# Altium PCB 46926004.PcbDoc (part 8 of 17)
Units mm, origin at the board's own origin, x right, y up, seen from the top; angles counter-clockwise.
Board outline 250 x 200 mm, 6 copper layers (Top Layer, INT1_GND, INT2_SIG, INT3_SIG, INT4_GND, Bottom Layer), stack 1.71 mm thick; 1450 components, 1293 nets, 5656 pads, 2307 vias.
Unrouted connection lines stored in the file: 2.
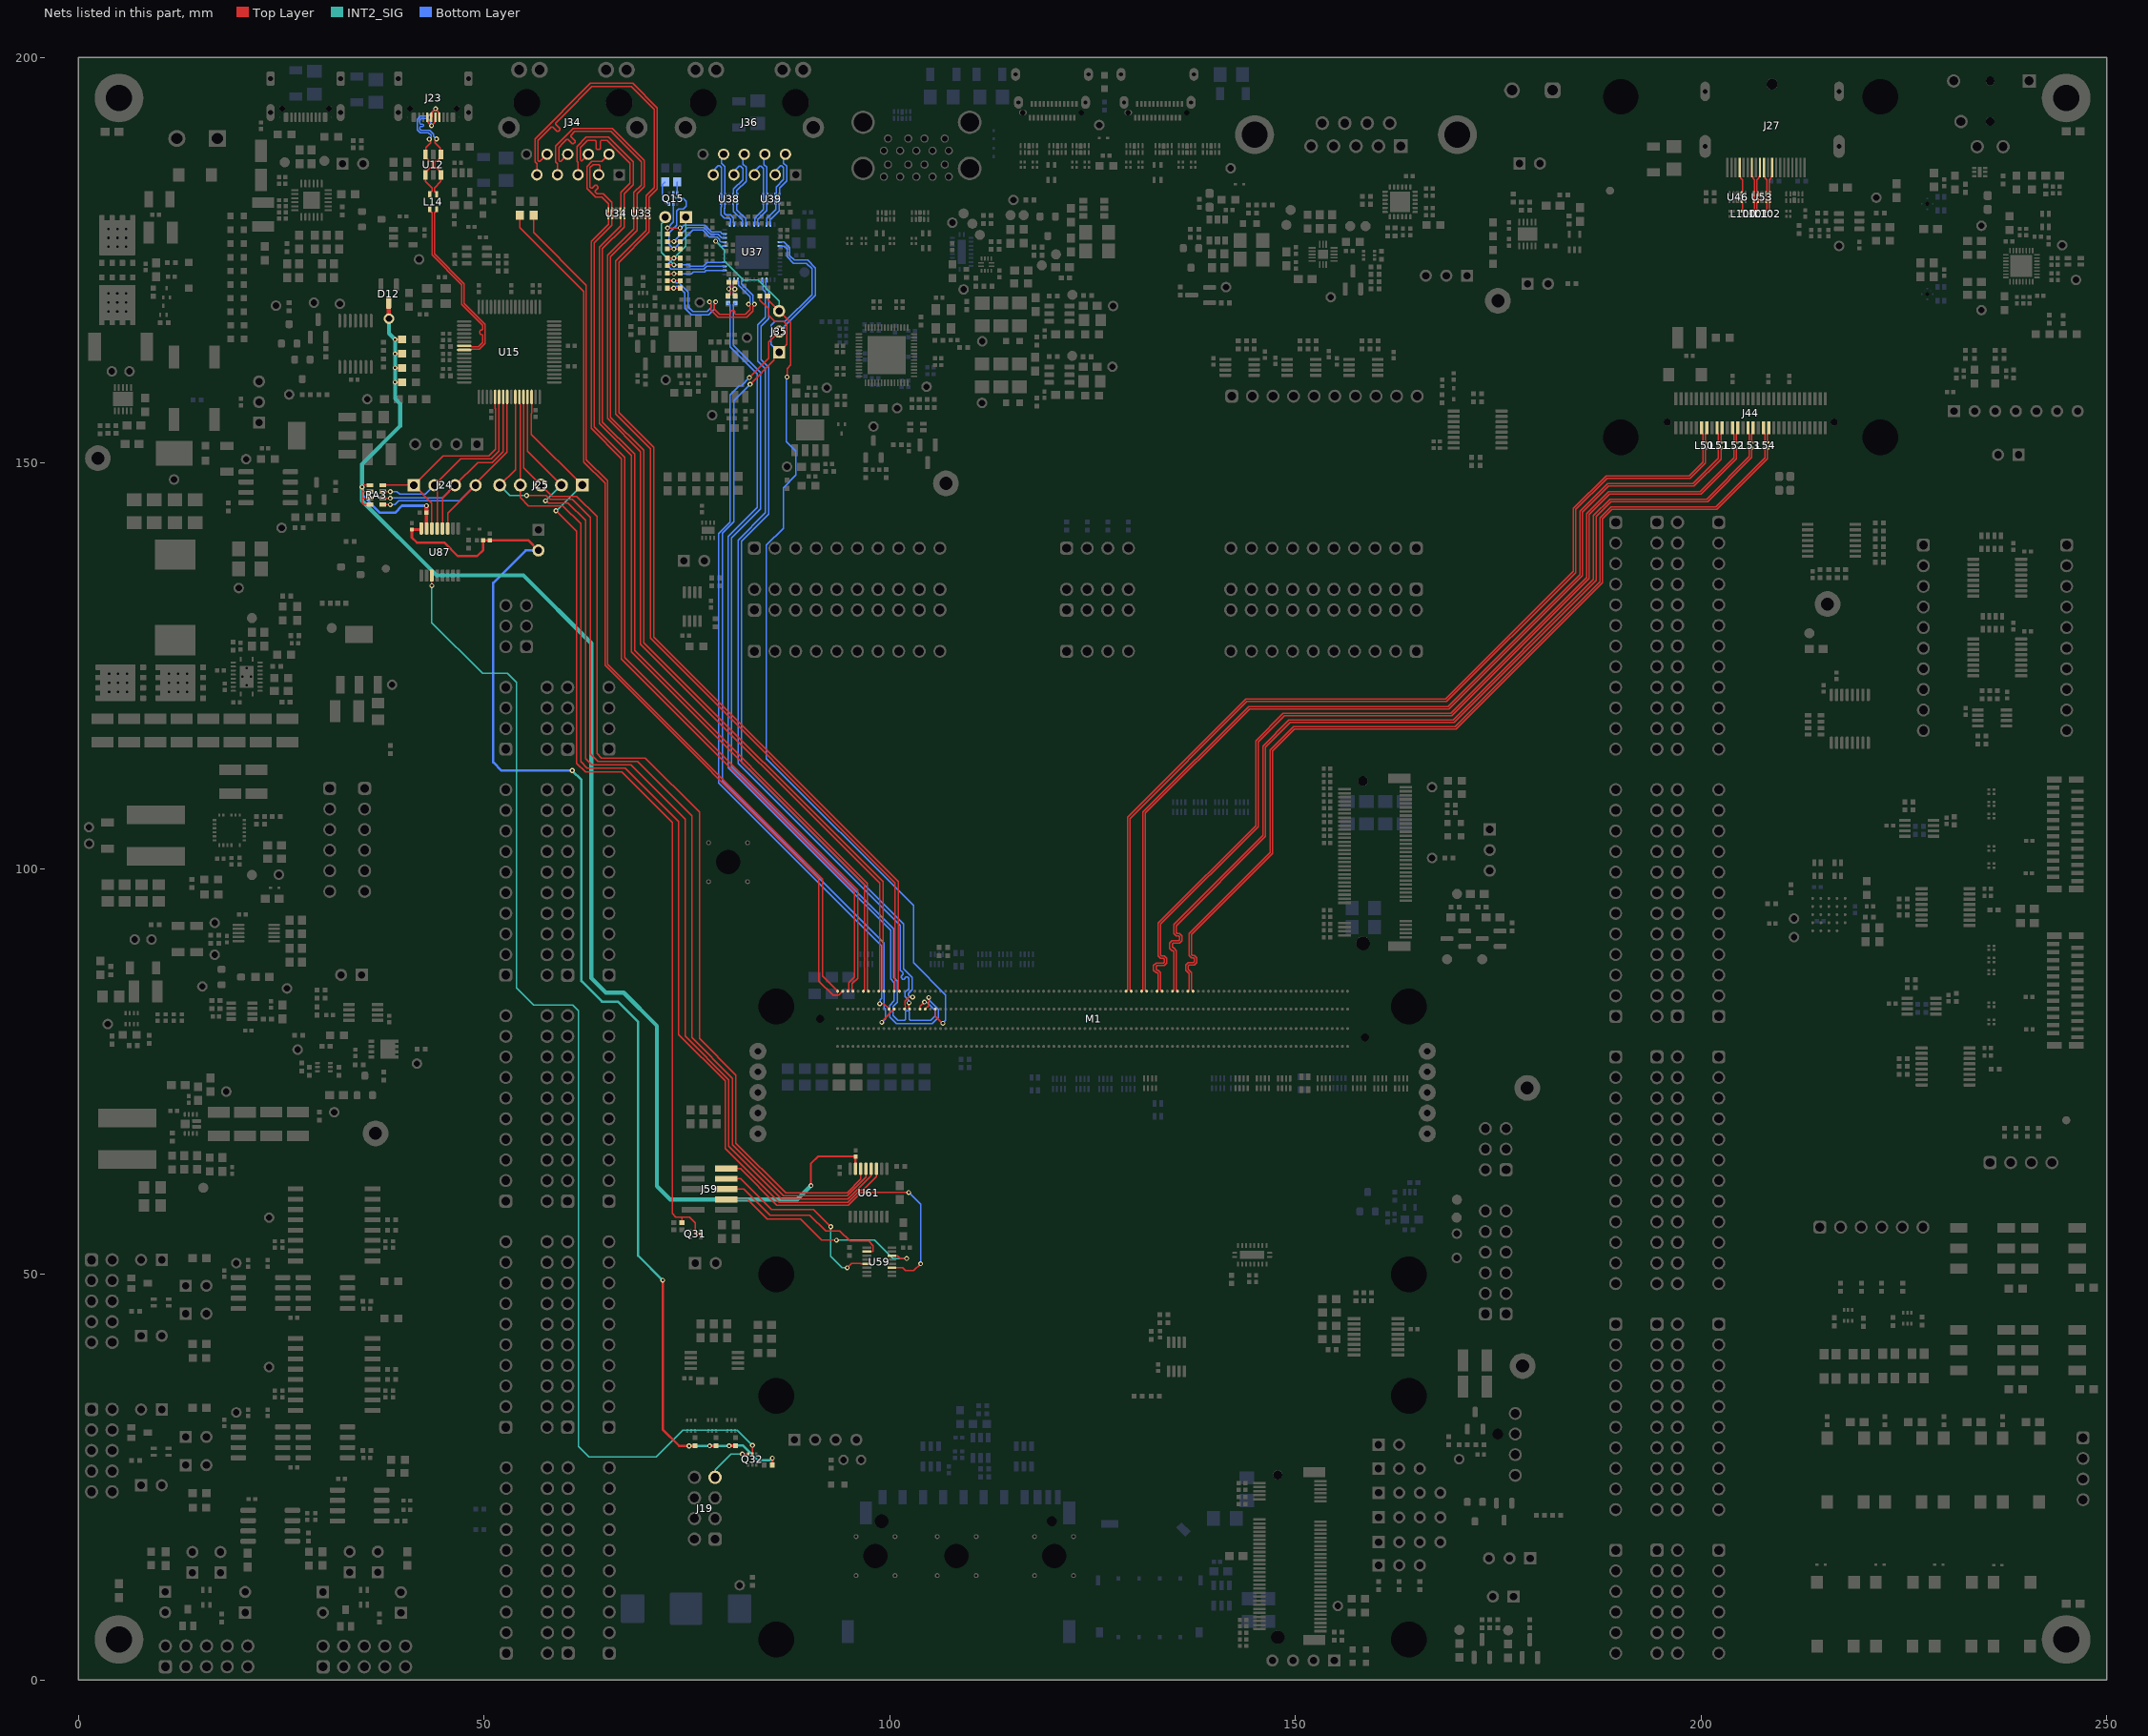
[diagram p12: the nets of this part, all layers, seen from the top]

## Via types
v1: diameter 0.6, hole 0.3, Top Layer to Bottom Layer, tented both sides, 2171 vias
v2: diameter 0.6, hole 0.3, Top Layer to Bottom Layer, 48 vias
v3: diameter 1, hole 0.5, Top Layer to Bottom Layer, tented both sides, 37 vias
v4: diameter 0.5, hole 0.2, Top Layer to Bottom Layer, tented both sides, 34 vias
v5: diameter 0.6, hole 0.3, Top Layer to Bottom Layer, tented bottom, 17 vias

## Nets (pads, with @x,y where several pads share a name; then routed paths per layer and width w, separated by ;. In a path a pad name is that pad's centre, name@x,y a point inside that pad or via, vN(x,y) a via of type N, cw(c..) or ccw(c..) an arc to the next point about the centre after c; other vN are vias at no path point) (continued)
DP__1_LANE1_P: J27.4 L100.4 U46.4 U46.7 | length 5.7
  Top Layer w0.15: J27.4@204.75,186.427 204.75,185.367 204.885,185.232 204.885,185.134 205.1,184.919 205.1,183.943 205.1,183.464 205,183.364 U46.7@205,183.184 205,183.004 205.1,182.904 205.1,182.631 205,182.53 U46.4@205,182.35 205,182.17 205.1,182.07 205.1,181.23 205.075,181.205 205.075,181.117 L100.4@205,181.043
DP__1_LANE2_N: J27.9 L101.3 U53.2 U53.9 | length 5.7
  Top Layer w0.15: L101.3@207,181.043 206.925,181.117 206.925,181.205 206.9,181.23 206.9,182.07 207,182.17 U53.2@207,182.35 207,182.53 206.9,182.63 206.9,182.904 207,183.004 U53.9@207,183.184 207,183.364 206.9,183.464 206.9,184.068 206.9,184.919 207.115,185.134 207.115,185.232 207.25,185.367 J27.9@207.25,186.427
DP__1_LANE2_P: J27.7 L101.4 U53.1 U53.10 | length 5.7
  Top Layer w0.15: J27.7@206.25,186.427 206.25,185.367 206.385,185.232 206.385,185.134 206.6,184.919 206.6,183.943 206.6,183.464 206.5,183.364 U53.10@206.5,183.184 206.5,183.004 206.6,182.904 206.6,182.631 206.5,182.53 U53.1@206.5,182.35 206.5,182.17 206.6,182.07 206.6,181.23 206.575,181.205 206.575,181.117 L101.4@206.5,181.043
DP__1_LANE3_N: J27.12 L102.3 U53.5 U53.6 | length 5.7
  Top Layer w0.15: L102.3@208.5,181.043 208.425,181.117 208.425,181.205 208.4,181.23 208.4,182.07 208.5,182.17 U53.5@208.5,182.35 208.5,182.53 208.4,182.63 208.4,182.904 208.5,183.004 U53.6@208.5,183.184 208.5,183.364 208.4,183.464 208.4,184.068 208.4,184.919 208.615,185.134 208.615,185.232 208.75,185.367 J27.12@208.75,186.427
DP__1_LANE3_P: J27.10 L102.4 U53.4 U53.7 | length 5.7
  Top Layer w0.15: J27.10@207.75,186.427 207.75,185.367 207.885,185.232 207.885,185.134 208.1,184.919 208.1,183.943 208.1,183.464 208,183.364 U53.7@208,183.184 208,183.004 208.1,182.904 208.1,182.631 208,182.53 U53.4@208,182.35 208,182.17 208.1,182.07 208.1,181.23 208.075,181.205 208.075,181.117 L102.4@208,181.043
DSI_1_CLK_N: L52.2 M1.A37 | length 117
  Top Layer w0.15: M1.A37@133.567,84.9 133.567,84.923 133.399,85.091 133.399,86.731 133.399,87.175 133.103,87.471 132.939,87.471 132.819,87.591 132.819,87.951 132.939,88.071 133.822,88.071 134.117,88.366 134.117,88.975 133.822,89.271 133.519,89.271 133.399,89.391 133.399,89.553 133.399,93.17 145.4,105.171 145.4,115.625 148.625,118.85 169.275,118.85 186.2,135.775 186.2,143.671 188.729,146.2 200,146.2 204.345,150.545 204.345,151.687 204.37,151.712 204.37,151.8 L52.2@204.445,151.875
DSI_1_CLK_P: L52.1 M1.A38 | length 117
  Top Layer w0.15: M1.A38@132.932,84.9 132.932,84.923 133.099,85.091 133.099,86.731 133.099,87.051 132.979,87.171 132.815,87.171 132.519,87.466 132.519,88.075 132.815,88.371 133.697,88.371 133.817,88.491 133.817,88.851 133.697,88.971 133.395,88.971 133.099,89.266 133.099,89.553 133.099,93.294 145.1,105.295 145.1,115.749 148.501,119.15 169.151,119.15 185.9,135.899 185.9,143.795 188.605,146.5 199.876,146.5 204.045,150.669 204.045,151.687 204.02,151.712 204.02,151.8 L52.1@203.945,151.875
DSI_1_D0_N: L50.2 M1.A43 | length 116.9
  Top Layer w0.15: M1.A43@129.763,84.9 129.763,84.923 129.595,85.091 129.595,106.195 144,120.6 168.65,120.6 184.565,136.515 184.565,144.291 188.409,148.135 198.674,148.135 200.535,149.996 200.535,151.687 200.56,151.712 200.56,151.8 L50.2@200.635,151.875
DSI_1_D0_P: L50.1 M1.A44 | length 116.9
  Top Layer w0.15: M1.A44@129.128,84.9 129.128,84.923 129.295,85.091 129.295,106.319 143.876,120.9 168.526,120.9 184.265,136.639 184.265,144.415 188.285,148.435 198.55,148.435 200.235,150.12 200.235,151.687 200.21,151.712 200.21,151.8 L50.1@200.135,151.875
DSI_1_D1_N: L51.2 M1.A40 | length 117
  Top Layer w0.15: M1.A40@131.668,84.9 131.668,84.923 131.5,85.091 131.5,106.851 144.349,119.7 168.946,119.7 185.35,136.104 185.35,143.921 188.597,147.168 199.118,147.168 202.44,150.49 202.44,151.687 202.465,151.712 202.465,151.8 L51.2@202.54,151.875
DSI_1_D1_P: L51.1 M1.A41 | length 117
  Top Layer w0.15: M1.A41@131.033,84.9 131.033,84.923 131.2,85.091 131.2,106.975 144.225,120 168.822,120 185.05,136.228 185.05,144.045 188.472,147.468 198.994,147.468 202.14,150.614 202.14,151.687 202.115,151.712 202.115,151.8 L51.1@202.04,151.875
DSI_1_D2_N: L53.2 M1.A34 | length 117
  Top Layer w0.15: M1.A34@135.472,84.9 135.472,84.923 135.304,85.091 135.304,89.544 135.304,89.922 135.008,90.217 134.935,90.217 134.815,90.337 134.815,90.697 134.935,90.817 135.748,90.817 136.044,91.113 136.044,91.722 135.748,92.017 135.424,92.017 135.304,92.137 135.304,92.3 135.304,92.978 146.3,103.974 146.3,115 149.325,118.025 169.55,118.025 187.05,135.525 187.05,143.421 188.892,145.263 200.825,145.263 206.25,150.688 206.25,151.687 206.275,151.712 206.275,151.8 L53.2@206.35,151.875
DSI_1_D2_P: L53.1 M1.A35 | length 117
  Top Layer w0.15: M1.A35@134.837,84.9 134.837,84.923 135.004,85.091 135.004,89.544 135.004,89.797 134.884,89.917 134.81,89.917 134.515,90.213 134.515,90.822 134.81,91.117 135.624,91.117 135.744,91.237 135.744,91.597 135.624,91.717 135.3,91.717 135.004,92.013 135.004,92.3 135.004,93.102 146,104.098 146,115.124 149.201,118.325 169.426,118.325 186.75,135.649 186.75,143.545 188.768,145.563 200.701,145.563 205.95,150.812 205.95,151.687 205.925,151.712 205.925,151.8 L53.1@205.85,151.875
DSI_1_D3_N: L54.2 M1.A31 | length 117
  Top Layer w0.15: M1.A31@137.377,84.9 137.377,84.923 137.209,85.091 137.209,86.545 137.209,87.21 136.913,87.505 136.793,87.625 136.793,87.985 136.913,88.105 137.53,88.105 137.825,88.401 137.825,89.01 137.53,89.305 137.329,89.305 137.209,89.425 137.209,89.588 137.209,91.895 147.2,101.886 147.2,114.495 149.905,117.2 169.825,117.2 187.85,135.225 187.85,143.121 189.029,144.3 201.939,144.3 208.155,150.516 208.155,151.687 208.18,151.712 208.18,151.8 L54.2@208.255,151.875
DSI_1_D3_P: L54.1 M1.A32 | length 117
  Top Layer w0.15: M1.A32@136.742,84.9 136.742,84.923 136.909,85.091 136.909,86.545 136.909,87.085 136.789,87.205 136.493,87.501 136.493,88.11 136.789,88.405 137.405,88.405 137.525,88.525 137.525,88.885 137.405,89.005 137.205,89.005 136.909,89.301 136.909,89.588 136.909,92.019 146.9,102.01 146.9,114.619 149.781,117.5 169.701,117.5 187.55,135.349 187.55,143.245 188.905,144.6 201.815,144.6 207.855,150.64 207.855,151.687 207.83,151.712 207.83,151.8 L54.1@207.755,151.875
DSI__CLK_N: J44.26 L52.3 | length 1.9
  Top Layer w0.15: L52.3@204.445,152.525 204.37,152.6 204.37,152.688 204.345,152.713 204.345,153.201 204.345,153.582 204.512,153.75 J44.26@204.512,154.35
DSI__CLK_P: J44.24 L52.4 | length 1.9
  Top Layer w0.15: J44.24@203.877,154.35 203.877,153.75 204.045,153.582 204.045,153.325 204.045,152.713 204.02,152.688 204.02,152.6 L52.4@203.945,152.525
DSI__D0_N: J44.14 L50.3 | length 1.9
  Top Layer w0.15: L50.3@200.635,152.525 200.56,152.6 200.56,152.688 200.535,152.713 200.535,153.582 200.702,153.75 J44.14@200.702,154.35
DSI__D0_P: J44.12 L50.4 | length 1.9
  Top Layer w0.15: J44.12@200.067,154.35 200.067,153.75 200.235,153.582 200.235,152.713 200.21,152.688 200.21,152.6 L50.4@200.135,152.525
DSI__D1_N: J44.20 L51.3 | length 1.9
  Top Layer w0.15: L51.3@202.54,152.525 202.465,152.6 202.465,152.688 202.44,152.713 202.44,153.324 202.44,153.582 202.607,153.75 J44.20@202.607,154.35
DSI__D1_P: J44.18 L51.4 | length 1.9
  Top Layer w0.15: J44.18@201.972,154.35 201.972,153.75 202.14,153.582 202.14,153.201 ; L51.4@202.04,152.525 202.115,152.6 202.115,152.688 202.14,152.713 202.14,153.2
DSI__D2_N: J44.32 L53.3 | length 1.9
  Top Layer w0.15: L53.3@206.35,152.525 206.275,152.6 206.275,152.688 206.25,152.713 206.25,153.201 206.25,153.582 206.417,153.75 J44.32@206.417,154.35
DSI__D2_P: J44.30 L53.4 | length 1.9
  Top Layer w0.15: J44.30@205.782,154.35 205.782,153.75 205.95,153.582 205.95,153.325 205.95,152.713 205.925,152.688 205.925,152.6 L53.4@205.85,152.525
DSI__D3_N: J44.38 L54.3 | length 1.9
  Top Layer w0.15: L54.3@208.255,152.525 208.18,152.6 208.18,152.684 208.151,152.713 208.151,153.578 208.322,153.75 J44.38@208.322,154.35
DSI__D3_P: J44.36 L54.4 | length 1.9
  Top Layer w0.15: J44.36@207.687,154.35 207.687,153.75 207.851,153.587 207.851,152.713 207.83,152.692 207.83,152.6 L54.4@207.755,152.525
ETH2_ACT: Q15.3 R178.1 | length 3.4
  Bottom Layer w0.15: R178.1@72.345,184.662 72,184.317 72,182.44 72.492,181.948 Q15.3@72.821,181.948
ETH2_D0_N: J36.8 U37.2 U38.2 U38.9 | length 9.9
  Bottom Layer w0.15: J36.8@79.525,188.065 79.286,187.826 79.286,186.936 79.65,186.572 79.65,183.017 U38.2@79.7,182.967 79.65,182.917 79.65,182.183 U38.9@79.7,182.133 79.65,182.083 79.65,181.43 79.587,181.367 79.587,180.783 79.786,180.584 80.35,180.584 80.75,180.184 80.75,179.654 80.8,179.604 U37.2@80.8,179.4
ETH2_D0_P: J36.9 U37.1 U38.1 U38.10 | length 9.8
  Bottom Layer w0.15: J36.9@78.255,185.525 78.494,185.764 78.494,186.282 78.872,186.66 78.996,186.66 79.25,186.406 79.25,183.017 U38.1@79.2,182.967 79.25,182.917 79.25,182.183 U38.10@79.2,182.133 79.25,182.083 79.25,181.595 79.187,181.533 79.187,180.617 79.621,180.184 80.184,180.184 80.35,180.018 80.35,179.654 80.3,179.604 U37.1@80.3,179.4
ETH2_D1_N: J36.6 U37.5 U38.5 U38.6 | length 9.9
  Bottom Layer w0.15: J36.6@82.065,188.065 81.92,187.92 81.92,186.859 82.3,186.479 82.3,184.742 81.15,183.592 81.15,183.017 U38.5@81.2,182.967 81.15,182.917 81.15,182.183 U38.6@81.2,182.133 81.15,182.083 81.15,181.211 82.25,180.111 82.25,179.654 82.3,179.604 U37.5@82.3,179.4
ETH2_D1_P: J36.7 U37.4 U38.4 U38.7 | length 9.9
  Bottom Layer w0.15: J36.7@80.795,185.525 81.034,185.764 81.034,186.204 81.46,186.63 81.584,186.63 81.9,186.314 81.9,184.908 80.75,183.758 80.75,183.292 80.75,183.017 U38.4@80.7,182.967 80.75,182.917 80.75,182.671 80.75,182.429 80.75,182.183 U38.7@80.7,182.133 80.75,182.083 80.75,181.808 80.75,181.045 81.85,179.945 81.85,179.654 81.8,179.604 U37.4@81.8,179.4
ETH2_D2_N: J36.4 U37.8 U39.2 U39.9 | length 9.4
  Bottom Layer w0.15: U37.8@83.8,179.4 83.8,179.604 83.75,179.654 83.75,180.018 84.85,181.118 84.85,182.116 U39.9@84.9,182.166 84.85,182.216 84.85,182.95 U39.2@84.9,183 84.85,183.05 84.85,186.456 84.518,186.788 84.518,187.978 J36.4@84.605,188.065
ETH2_D2_P: J36.5 U37.7 U39.1 U39.10 | length 9.4
  Bottom Layer w0.15: U37.7@83.3,179.4 83.3,179.604 83.35,179.654 83.35,180.184 84.45,181.284 84.45,182.116 U39.10@84.4,182.166 84.45,182.216 84.45,182.95 U39.1@84.4,183 84.45,183.05 84.45,186.29 84.111,186.629 83.987,186.629 83.574,186.216 83.574,185.764 J36.5@83.335,185.525
ETH2_D3_N: J36.2 U37.11 U39.5 U39.6 | length 9.8
  Bottom Layer w0.15: U37.11@85.3,179.4 85.3,179.604 85.25,179.654 85.25,180.018 85.338,180.106 85.348,180.106 86.35,181.108 86.35,182.116 U39.6@86.4,182.166 86.35,182.216 86.35,182.95 U39.5@86.4,183 86.4,183.872 87.321,184.793 87.321,186.578 86.924,186.974 86.924,187.844 J36.2@87.145,188.065
ETH2_D3_P: J36.3 U37.10 U39.4 U39.7 | length 9.8
  Bottom Layer w0.15: U37.10@84.8,179.4 84.8,179.604 84.85,179.654 84.85,180.184 85.172,180.506 85.182,180.506 85.95,181.274 85.95,181.841 85.95,182.116 U39.7@85.9,182.166 85.95,182.216 85.95,182.462 85.95,182.704 U39.4@85.95,182.95 ; J36.3@85.875,185.525 86.114,185.764 86.114,186.234 86.544,186.664 86.669,186.664 86.921,186.412 86.921,184.958 86,184.038 86,183.288 85.9,183.188 U39.4@85.9,183
ETH2_GPIO_0: J28.1 R168.1 R219.2 U37.39 | length 15.7
  Top Layer w0.15: R168.1@72.595,175.262 v1(73.395,175.262) R219.2@74.17,175.262
  INT2_SIG w0.15: v1(73.395,175.262) 74.872,176.739 J28.1@74.872,180.315
  Bottom Layer w0.15: v1(73.395,175.262) 72.754,174.621 72.754,174.198 73.052,173.9 77.071,173.9 77.421,174.25 U37.39@79.65,174.25
ETH2_GPIO_1: J28.2 R450.1 R451.2 U37.40 | length 14.9
  Top Layer w0.15: R450.1@72.595,174.337 72.683,174.425 v1(73.395,174.425) ; v1@73.395,174.387 74.12,174.387 R451.2@74.17,174.337
  INT2_SIG w0.15: J28.2@72.332,180.315 72.332,179.949 71.85,179.467 71.85,175.97 v1(73.395,174.425)
  Bottom Layer w0.15: v1(73.395,174.425) 75.236,174.425 75.398,174.263 77.009,174.263 77.496,174.75 U37.40@79.65,174.75
ETH2_LED_0: Q15.2 R162.1 R163.2 U37.47 | length 12.4
  Top Layer w0.15: R162.1@72.595,178.237 v1(72.595,178.985) 72.599,178.989 74.166,178.989 v1(74.17,178.993) R163.2@74.17,178.237
  Bottom Layer w0.15: v1(72.595,178.985) 73.321,179.711 Q15.2@73.321,181.948 ; v1(74.17,178.993) 74.269,178.993 74.591,179.315 77.2,179.315 78.03,178.485 79.115,178.485 79.333,178.267 79.633,178.267 U37.47@79.65,178.25
ETH2_LED_1: R164.1 R167.2 U37.46 | length 9.1
  Top Layer w0.15: R164.1@72.595,177.312 v1(73.395,177.312) R167.2@74.17,177.312
  Bottom Layer w0.15: v1(73.395,177.312) 75.098,179.015 77.076,179.015 77.906,178.185 78.865,178.185 79.283,177.767 79.633,177.767 U37.46@79.65,177.75
ETH2_LED_2: Q15.5 R158.1 R161.2 U37.45 | length 19
  Top Layer w0.15: R158.1@72.595,176.387 v1(73.395,176.387) R161.2@74.17,176.387
  Bottom Layer w0.15: Q15.5@73.321,183.298 73.321,182.973 73.615,182.678 74.491,182.678 74.904,182.265 74.904,181.658 74.569,181.322 73.971,181.322 73.729,181.081 73.729,179.309 72.821,178.401 72.821,176.961 v1(73.395,176.387) 75.723,178.715 76.951,178.715 77.791,177.875 78.747,177.875 79.054,177.567 79.054,177.388 79.192,177.25 U37.45@79.65,177.25
ETH2_LINK: Q15.6 R177.1 | length 1.4
  Bottom Layer w0.15: Q15.6@73.821,183.298 R177.1@73.821,184.662
ETH_1_LED1: M1.A99 R147.1 | length 113.5
  Top Layer w0.15: R147.1@54.4,180.557 54.4,179.043 62.3,171.143 62.3,150.11 64.9,147.51 64.9,125.074 91.275,98.699 91.275,86.16 93.012,84.422 93.725,84.422 M1.A99@94.203,84.9
ETH_1_LED2: M1.A100 R146.1 | length 111.1
  Top Layer w0.15: R146.1@56,180.472 56.105,180.367 56.105,178.411 62.6,171.916 62.6,150.4 65.2,147.8 65.2,125.198 91.714,98.684 91.714,86.753 M1.A100@93.568,84.9
ETH_1_MDI0_N: J34.8 M1.A89 U33.2 U33.9 | length 148.7
  Top Layer w0.15: J34.8@57.775,188.065 56.895,187.185 56.77,187.185 56.66,187.295 56.66,189.769 57.9,191.009 58.307,191.416 58.448,191.416 58.997,190.867 59.138,190.867 59.35,191.08 59.35,191.221 58.802,191.77 58.802,191.911 59.913,193.022 63.291,196.4 68.14,196.4 70.95,193.59 70.95,183.95 69.95,182.95 69.95,181.259 U33.2@69.9,181.209 69.95,181.159 U33.9@69.95,180.625 ; U33.9@69.9,180.375 69.95,180.325 69.95,178.646 66.2,174.896 66.2,156.068 70.5,151.768 70.5,128.416 100.67,98.246 100.67,85.073 100.592,84.995 M1.A89@100.592,84.93
ETH_1_MDI0_P: J34.9 M1.A88 U33.1 U33.10 | length 148.7
  Top Layer w0.15: J34.9@56.505,185.525 56.505,186.884 56.26,187.129 56.26,189.935 63.125,196.8 68.306,196.8 71.35,193.756 71.35,183.784 70.35,182.784 70.35,181.259 U33.1@70.4,181.209 70.35,181.159 U33.10@70.35,180.625 ; U33.10@70.4,180.375 70.35,180.325 70.35,178.48 66.6,174.73 66.6,156.233 70.9,151.933 70.9,128.582 101.07,98.412 101.07,85.073 101.188,84.956 M1.A88@101.188,84.9
ETH_1_MDI1_N: J34.6 M1.A92 U33.5 U33.6 | length 134.7
  Top Layer w0.15: J34.6@60.315,188.065 59.435,187.185 59.31,187.185 59.2,187.295 59.2,188.915 59.765,189.48 60.172,189.887 60.313,189.887 60.845,189.354 60.987,189.354 61.199,189.566 61.199,189.708 60.667,190.24 60.667,190.382 61.15,190.865 61.2,190.865 65.635,190.865 69.37,187.13 69.37,184.27 68.475,183.375 U33.5@68.475,181.503 ; U33.6@68.4,180.375 68.45,180.325 68.45,178.853 65.2,175.603 65.2,155.503 69.3,151.403 69.3,127.7 98.765,98.235 98.765,85.073 98.648,84.956 M1.A92@98.648,84.9 ; U33.5@68.4,181.209 68.45,181.159 68.45,180.913 U33.6@68.45,180.625
ETH_1_MDI1_P: J34.7 M1.A91 U33.4 U33.7 | length 134.7
  Top Layer w0.15: J34.7@59.045,185.525 59.045,186.884 58.8,187.129 58.8,189.081 60.984,191.265 65.801,191.265 69.77,187.296 69.77,184.104 68.875,183.209 U33.4@68.875,181.503 ; U33.7@68.85,180.625 68.85,181.159 U33.4@68.9,181.209 ; U33.7@68.9,180.375 68.85,180.325 68.85,180.05 68.85,178.687 65.6,175.437 65.6,155.668 69.7,151.568 69.7,127.866 99.165,98.401 99.165,85.073 99.283,84.956 M1.A91@99.283,84.9
ETH_1_MDI2_N: J34.4 M1.A95 U34.2 U34.9 | length 129.7
  Top Layer w0.15: J34.4@62.855,188.065 62.063,187.273 61.938,187.273 61.851,187.361 61.851,188.872 62.748,189.769 63.142,189.769 63.717,189.769 63.817,189.669 63.817,188.783 63.917,188.683 64.217,188.683 64.317,188.783 64.317,189.669 64.417,189.769 64.695,189.769 65.181,189.769 68,186.95 68,184.5 66.85,183.35 66.85,181.915 66.85,181.262 U34.2@66.8,181.212 ; U34.2@66.85,181.212 66.85,179.271 64.2,176.621 64.2,154.903 68.15,150.953 68.15,126.75 96.86,98.04 96.86,85.073 96.743,84.956 M1.A95@96.743,84.9
ETH_1_MDI2_P: J34.5 M1.A94 U34.1 U34.10 | length 129.7
  Top Layer w0.15: J34.5@61.585,185.525 61.585,187.06 61.451,187.195 61.451,189.038 62.582,190.169 65.346,190.169 68.4,187.116 68.4,184.334 67.25,183.184 67.25,181.749 67.25,181.262 U34.1@67.3,181.212 67.25,181.162 U34.10@67.25,180.328 ; U34.10@67.3,180.378 U34.10@67.25,180.328 ; M1.A94@97.378,84.9 97.378,84.956 97.26,85.073 97.26,98.206 68.55,126.916 68.55,151.118 64.6,155.068 64.6,176.455 67.25,179.105 U34.10@67.25,180.328
ETH_1_MDI3_N: J34.2 M1.A98 U34.5 U34.6 | length 121.3
  Top Layer w0.15: U34.6@65.3,180.378 65.35,180.328 65.35,179.458 63.2,177.308 63.2,154.293 66.95,150.543 66.95,125.875 95.635,97.189 95.635,86.66 94.955,85.979 94.955,85.073 94.838,84.956 M1.A98@94.838,84.9 ; U34.6@65.35,180.628 65.35,180.915 65.35,181.162 U34.5@65.3,181.212 65.35,181.262 65.35,181.984 64.534,182.8 63.734,182.8 62.666,183.868 62.666,186.568 63.268,187.17 64.5,187.17 64.987,187.657 64.987,187.671 64.965,187.693 64.965,188.065 J34.2@65.395,188.065
ETH_1_MDI3_P: J34.3 M1.A97 U34.4 U34.7 | length 121.3
  Top Layer w0.15: J34.3@64.125,185.525 64.274,185.674 64.274,186.682 64.186,186.77 63.434,186.77 63.066,186.402 63.066,184.074 63.066,184.034 63.216,183.884 63.357,183.884 63.712,184.239 63.853,184.239 64.065,184.027 64.065,183.885 63.711,183.531 63.711,183.389 63.811,183.289 63.9,183.2 64.193,183.2 64.7,183.2 65.75,182.15 65.75,181.537 65.75,181.262 U34.4@65.8,181.212 65.75,181.162 U34.7@65.75,180.628 ; U34.7@65.8,180.378 65.75,180.328 65.75,180.052 65.75,179.292 63.6,177.142 63.6,154.459 67.35,150.709 67.35,126.041 96.035,97.355 96.035,86.494 95.355,85.814 95.355,85.073 95.473,84.956 M1.A97@95.473,84.9
ETH_2_RX_CTRL: R156.2 R157.2 U37.38 | length 8.1
  Top Layer w0.18: R156.2@72.595,173.412 72.67,173.337 v1(73.395,173.337) 74.095,173.337 R157.2@74.17,173.412
  Bottom Layer w0.15: v1(73.395,173.337) 75.562,173.337 75.806,173.581 77.176,173.581 77.345,173.75 U37.38@79.65,173.75
ETH_2_XGMII_CO_N: R150.1 R151.2 U37.34 | length 21.4
  Top Layer w0.15: R150.1@72.595,171.562 v1(73.37,171.562) R151.2@74.17,171.562 ; v1(78.535,169.872) 78.535,169.75 78.36,169.575 78.36,169.001 79.009,168.351 79.725,168.351 80.28,168.351 80.38,168.451 80.38,168.696 80.48,168.796 80.78,168.796 80.88,168.696 80.88,168.451 80.98,168.351 81.555,168.351 82.182,168.351 82.765,168.933 82.765,169.278 82.59,169.453 v1(82.59,169.575)
  Bottom Layer w0.15: v1(73.37,171.562) 73.42,171.562 73.683,171.825 73.85,171.825 74.725,170.949 74.725,169.102 75.559,168.268 77.66,168.268 78.362,168.97 78.362,169.302 78.36,169.304 78.36,169.575 78.535,169.75 v1(78.535,169.872) ; U37.34@81.3,172.6 81.3,172.396 81.35,172.346 81.35,171.909 82.765,170.495 82.765,169.872 82.59,169.697 v1(82.59,169.575)
ETH_2_XGMII_CO_P: R62.1 R149.2 U37.33 | length 21.4
  Top Layer w0.15: R62.1@72.595,172.487 v1(73.37,172.487) R149.2@74.17,172.487 ; v1(77.785,169.869) 77.785,169.747 77.96,169.572 77.96,168.835 78.844,167.951 82.348,167.951 83.165,168.768 83.165,169.278 83.34,169.453 v1(83.34,169.575)
  Bottom Layer w0.15: v1(73.37,172.487) 73.42,172.487 73.683,172.225 74.016,172.225 75.125,171.115 75.125,169.268 75.725,168.668 77.495,168.668 77.96,169.133 77.96,169.572 77.785,169.747 v1(77.785,169.869) ; U37.33@81.8,172.6 81.8,172.396 81.75,172.346 81.75,172.075 83.165,170.66 83.165,169.872 83.34,169.697 v1(83.34,169.575)
ETH_2_XGMII_INT#: J35.3 M1.B81 R174.1 U37.44 | length 118.8
  Top Layer w0.15: R174.1@84.958,170.583 84.958,170.141 J35.3@86.36,168.74 87.79,167.31 87.79,162.075 87.34,161.625 v1(87.34,160.605) ; M1.B81@105.632,82.7 105.632,81.768 106.46,80.94 v1(106.55,80.94)
  INT2_SIG w0.15: v1(78.529,177.35) 79.61,176.269 79.61,174.89 81.94,172.56 83.788,172.56 86.36,169.989 J35.3@86.36,168.74
  Bottom Layer w0.15: v1(78.529,177.35) 78.529,177.346 79.125,176.75 U37.44@79.65,176.75 ; v1(87.34,160.605) 87.265,160.53 87.265,152.653 88.425,151.492 88.425,148.525 86.871,146.97 86.871,141.971 84.81,139.91 84.81,113.578 102.914,95.475 102.914,88.397 106.903,84.409 106.903,81.33 106.55,80.977 v1(106.55,80.94)
ETH_2_XGMII_MDC: J35.2 M1.B90 U37.16 | length 111.9
  Top Layer w0.15: v1(82.696,160.525) 85.1,162.929 85.1,164.94 J35.2@86.36,166.2 ; v1(98.765,83.355) 99.262,83.355 M1.B90@99.917,82.7
  Bottom Layer w0.15: v1(82.696,160.525) 81.712,159.542 81.439,159.542 80.32,158.423 80.32,142.72 78.915,141.315 78.915,110.579 99.011,90.482 99.011,84.023 98.851,83.863 98.851,83.441 v1(98.765,83.355) ; J35.2@86.36,166.2 90.819,170.66 90.819,174.055 89.874,175 88.222,175 87.64,175.582 87.64,176.57 86.96,177.25 U37.16@86.45,177.25
ETH_2_XGMII_MDIO: J35.1 M1.B89 R175.1 U37.17 | length 124.8
  Top Layer w0.15: v1(82.787,159.711) 85.75,162.674 85.75,163.05 87.335,164.635 87.335,167.036 86.928,167.443 85.844,167.443 85.075,168.211 85.075,169.007 83.988,170.094 R175.1@83.988,170.575 ; v1(99.014,81.07) 99.014,81.162 M1.B89@100.552,82.7
  Bottom Layer w0.15: v1(82.787,159.711) 80.8,157.724 80.8,142.776 79.375,141.351 79.375,110.79 99.311,90.853 99.311,82.849 99.46,82.7 99.46,81.516 v1(99.014,81.07) ; J35.1@86.36,163.66 85.375,164.644 85.375,166.974 85.844,167.443 87.098,167.443 90.394,170.738 90.394,173.961 89.715,174.641 88.157,174.641 87.34,175.458 87.34,176.376 86.966,176.75 U37.17@86.45,176.75
ETH_2_XGMII_RX_N: C188.2 M1.B83 | length 110.9
  Top Layer w0.15: M1.B83@104.362,82.7 104.8,83.138 v1(104.8,84.129)
  Bottom Layer w0.15: C188.2@80.15,169.675 C188.2@80.1,169.725 80.325,169.5 80.325,164.323 83.68,160.968 83.68,144.519 80.1,140.939 80.1,112.434 100.089,92.446 100.089,86.449 100.556,85.982 100.556,83.722 100,83.166 100,81.75 100.844,80.906 105.232,80.906 105.975,81.65 105.975,82.695 104.886,83.784 104.886,84.043 v1(104.8,84.129)
ETH_2_XGMII_RX_P: C147.2 M1.B84 | length 110.8
  Top Layer w0.15: M1.B84@103.727,82.7 103.727,83.023 v1(104.275,83.571)
  Bottom Layer w0.15: C147.2@80.95,169.725 80.725,169.5 80.725,164.489 84.08,161.134 84.08,144.353 80.5,140.773 80.5,112.6 100.489,92.611 100.489,86.615 100.956,86.148 100.956,83.556 100.4,83 100.4,81.916 101.009,81.306 101.426,81.306 101.819,81.306 101.919,81.406 101.919,82.413 102.019,82.513 102.319,82.513 102.419,82.413 102.419,81.406 102.519,81.306 103.094,81.306 105.066,81.306 105.575,81.815 105.575,82.529 104.62,83.485 104.361,83.485 v1(104.275,83.571)
ETH_2_XGMII_SO_N: C188.1 R154.1 R155.2 U37.36 | length 4.3
  Top Layer w0.15: R155.2@80.1,170.625 80.3,170.825 80.3,170.925 80.325,170.95 80.325,171.178 80.15,171.353 v1(80.15,171.475) 80.15,171.575 80.325,171.75 80.325,172.1 R154.1@80.15,172.275
  Bottom Layer w0.15: C188.1@80.1,170.525 80.325,170.75 80.325,171.178 80.15,171.353 v1(80.15,171.475) 80.15,171.597 80.35,171.797 80.35,172.346 80.3,172.396 U37.36@80.3,172.6
ETH_2_XGMII_SO_P: C147.1 R152.1 R153.2 U37.35 | length 4.3
  Top Layer w0.15: R152.1@80.92,172.28 80.725,172.085 80.725,171.747 80.9,171.572 v1(80.9,171.45) 80.9,171.328 80.725,171.153 80.725,170.925 80.725,170.85 R153.2@80.95,170.625
  Bottom Layer w0.15: U37.35@80.8,172.6 80.8,172.396 80.75,172.346 80.75,171.722 80.9,171.572 v1(80.9,171.45) 80.9,171.328 80.725,171.153 80.725,170.75 C147.1@80.95,170.525
ETH_2_XGMII_TX_N: M1.B86 U37.28 | length 102.3
  Top Layer w0.15: v1(102.38,83.475) 102.34,83.434 102.34,82.873 102.45,82.763 M1.B86@102.45,82.75
  Bottom Layer w0.15: U37.28@84.3,172.6 84.3,172.396 84.35,172.346 84.35,171.389 84.675,171.064 84.675,167.99 83.728,167.043 83.728,162.581 84.675,161.634 84.675,143.875 81.3,140.5 81.3,113 101.3,93 101.3,87.5 101.561,87.239 101.661,87.139 101.661,86.998 101.398,86.735 101.398,86.594 101.61,86.382 101.752,86.382 102.014,86.644 102.156,86.644 102.209,86.591 102.342,86.458 102.342,85.222 101.893,84.773 101.893,84.24 102.298,83.835 102.298,83.557 v1(102.38,83.475)
ETH_2_XGMII_TX_P: M1.B87 U37.27 | length 102.3
  Top Layer w0.15: M1.B87@101.782,82.708 101.782,82.716 101.94,82.873 101.94,83.103 101.855,83.188 101.855,83.692 102.291,84.129 102.759,84.129 v1(102.816,84.186)
  Bottom Layer w0.15: U37.27@84.8,172.6 84.8,172.396 84.75,172.346 84.75,171.555 85.075,171.23 85.075,167.824 84.128,166.878 84.128,162.746 85.075,161.8 85.075,143.709 81.7,140.334 81.7,113.166 101.7,93.166 101.7,87.666 102.742,86.624 102.742,85.056 102.293,84.607 102.293,84.405 102.443,84.255 102.747,84.255 v1(102.816,84.186)
EXT_JTAG_TCK: J59.4 U59.5 | length 24.8
  Top Layer w0.15: J59.4@79.335,61.77 79.365,61.8 81.63,61.8 85.455,57.975 90.629,57.975 v1(92.729,55.875) ; v1(94.759,50.798) 94.759,50.803 95.306,51.35 96.417,51.35 96.467,51.3 U59.5@97.187,51.3
  INT2_SIG w0.15: v1(92.729,55.875) 92.729,52.212 94.143,50.798 v1(94.759,50.798)
EXT_JTAG_TDI: J59.8 U59.14 | length 27.7
  Top Layer w0.15: J59.8@79.335,59.23 82.47,59.23 84.886,56.814 89.011,56.814 91.613,54.212 v1(93.441,54.212) ; U59.14@100.263,52.3 100.291,52.272 100.938,52.272 101.264,51.946 102.084,51.946 v1(102.088,51.95)
  INT2_SIG w0.15: v1(93.441,54.212) 98.129,54.212 100.391,51.95 v1(102.088,51.95)
EXT_JTAG_TDO: J59.6 U59.2 | length 23
  Top Layer w0.15: J59.6@79.335,60.5 82.025,60.5 85.225,57.3 90.157,57.3 92.107,55.35 93.855,55.35 95.116,54.089 97.404,54.089 97.949,53.543 97.949,52.888 97.862,52.8 U59.2@97.187,52.8
EXT_JTAG_TMS: J59.2 U59.11 | length 39
  Top Layer w0.15: J59.2@79.335,63.04 81.588,63.04 86.089,58.539 94.914,58.539 96.464,60.089 v1(102.342,60.089) ; U59.11@100.263,50.8 101.577,50.8 101.927,50.45 102.96,50.45 v1(103.81,51.3)
  Bottom Layer w0.15: v1(102.342,60.089) 103.81,58.621 v1(103.81,51.3)
FORCE_OFF#_1V8: Q32.5 U87.3 | length 144.6
  Top Layer w0.15: v1(43.565,134.876) U87.3@43.565,136.136 ; Q32.5@83.075,27.85 v1(83.075,28.915)
  INT2_SIG w0.15: v1(43.565,134.876) 43.565,130.335 49.815,124.085 52.875,124.085 54.01,122.95 54.01,85.295 56.105,83.2 60.929,83.2 61.659,82.47 61.659,28.794 62.952,27.501 71.203,27.501 74.485,30.784 81.206,30.784 v1(83.075,28.915)
FORCE_OFF_MOCI#: J19.7 Q32.6 | length 5.8
  Top Layer w0.18: v1(81.825,27.85) Q32.6@82.575,27.85
  INT2_SIG w0.15: J19.7@78.469,24.985 78.469,25.884 80.435,27.85 v1(81.825,27.85)
FT_1V8: C390.2 C391.2 C392.2 J63.2 R92.1 R93.1 R94.1 R467.1 U87.16 | length 165.8
  Top Layer w0.3: U87.16@42.265,141.936 42.129,141.8 C390.2@41.1,141.8 41.1,140.817 41.717,140.2 45.095,140.2 46.755,138.54 49.14,138.54 49.9,139.3 C391.2@49.9,140.5 C392.2@50.7,140.5 55.43,140.5 J63.2@56.7,139.23 ; v1(72.015,49.279) 72.015,30.9 74.063,28.852 v1(75.26,28.852) 75.267,28.858 76.002,28.858 R93.1@76.009,28.865 ; v1(77.8,28.861) 77.811,28.872 78.659,28.872 R94.1@78.67,28.884 ; v1(80.2,28.87) 80.207,28.877 80.968,28.877 R92.1@80.975,28.884 ; R467.1@85.525,26.5 v1(85.525,27.35)
  INT2_SIG w0.3: v1(60.864,112.1) 62.007,110.958 62.007,86.142 64.535,83.613 66.487,83.613 69,81.1 69,52.294 v1(72.015,49.279) ; v1(75.26,28.852) 75.265,28.856 77.795,28.856 77.805,28.865 80.186,28.865 80.191,28.861 80.214,28.884 81.916,28.884 83.731,27.069 85.244,27.069 v1(85.525,27.35)
  Bottom Layer w0.3: J63.2@56.7,139.23 55.123,139.23 51.125,135.232 51.125,113.115 52.14,112.1 v1(60.864,112.1)
FT_3V3: C240.2 C389.2 D12.3 L16.1 L17.1 L18.1 L19.1 RA3.1 RA3.2 RA3.3 RA3.4 U61.15 U87.15 X30.1 | length 187.1
  Top Layer w0.15: RA3.4@35.925,144.875 35.2,144.875 34.965,145.11 34.965,145.675 ; RA3.3@35.925,145.675 34.965,145.675 ; RA3.2@35.925,146.475 34.965,146.475 ; RA3.1@35.925,147.275 35.924,147.274 35.19,147.274 v1(34.965,147.048) 34.965,146.475 ; 34.965,145.675 34.965,146.475
  Top Layer w0.25: v1(39.03,159.975) L19.1@40.015,159.975 ; v1(39.03,161.725) L17.1@40.015,161.725 ; v1(39.03,163.475) L18.1@40.015,163.475 ; v1(39.03,165.225) L16.1@40.015,165.225 ; v1(90.298,60.939) 90.298,63.67 91.153,64.525 95.775,64.525 C240.2@95.8,64.5 ; U61.15@95.764,63.314 C240.2@95.764,64.5
  Top Layer w0.4: C389.2@42.89,143.871 42.89,141.961 U87.15@42.915,141.936
  Top Layer w0.5: D12.3@38.245,169.784 38.26,169.769 38.26,167.814 X30.1@38.275,167.799 ; C389.2@42.89,143.871 v1@42.89,144.713
  INT2_SIG w0.5: X30.1@38.275,167.799 38.275,165.98 v1(39.03,165.225) v1(39.03,163.475) v1(39.03,161.725) v1(39.03,159.975) 39.03,157.935 39.65,157.315 39.65,154.546 34.965,149.861 v1(34.965,147.048) 34.965,145.346 44.151,136.16 54.847,136.16 63.221,127.786 63.221,86.519 65.026,84.715 67.21,84.715 71.3,80.625 71.3,60.873 72.943,59.23 88.589,59.23 v1(90.298,60.939)
  Bottom Layer w0.3: v1(34.965,147.048) 34.965,146.066 37.155,143.876 39.021,143.876 39.883,144.738 v1(42.915,144.738)
FT_USB_N: L14.1 U15.7 | length 22.1
  Top Layer w0.15: L14.1@43.3,181.28 43.3,181.105 43.575,180.83 43.575,175.659 47.25,171.984 47.25,169.54 49.823,166.967 49.823,166.875 49.823,166.488 49.723,166.388 49.557,166.388 49.457,166.288 49.457,165.988 49.557,165.888 49.723,165.888 49.823,165.788 49.823,165.713 49.823,164.875 49.298,164.35 48.441,164.35 48.341,164.45 U15.7@47.55,164.45
FT_USB_P: L14.4 U15.8 | length 22.1
  Top Layer w0.15: L14.4@44.15,181.28 44.15,181.105 43.875,180.83 43.875,175.783 47.55,172.108 47.55,169.664 50.123,167.092 50.123,164.751 49.422,164.05 48.441,164.05 48.341,163.95 U15.8@47.55,163.95
FTA_GPIOL0: J24.1 RA3.8 U15.21 U87.14 | length 28.4
  Top Layer w0.15: RA3.8@37.525,147.275 J24.1@41.34,147.275 ; U87.14@43.565,141.936 43.565,145.05 J24.1@41.34,147.275 ; U15.21@51.35,158.15 51.35,156.753 51.39,156.713 51.39,151.69 50.575,150.875 44.94,150.875 J24.1@41.34,147.275
FTA_GPIOL1: J24.2 RA3.7 U15.22 U87.13 | length 28.8
  Top Layer w0.15: RA3.7@37.525,146.475 v1(38.443,146.475) ; U87.13@44.215,141.936 44.215,146.94 J24.2@43.88,147.275 47.13,150.525 50.888,150.525 51.85,151.487 U15.22@51.85,158.15
  Bottom Layer w0.15: v1(38.443,146.475) 39.275,146.475 39.596,146.154 42.759,146.154 J24.2@43.88,147.275
FTA_GPIOL2: J24.3 RA3.6 U15.23 U87.12 | length 29.9
  Top Layer w0.15: RA3.6@37.525,145.675 v1(38.443,145.675) ; U87.12@44.865,141.936 44.865,145.72 J24.3@46.42,147.275 49.22,150.075 51,150.075 52.35,151.425 U15.23@52.35,158.15
  Bottom Layer w0.15: v1(38.443,145.675) 38.494,145.725 44.87,145.725 J24.3@46.42,147.275
FTA_GPIOL3: J24.4 RA3.5 U15.24 U87.11 | length 31.7
  Top Layer w0.15: RA3.5@37.525,144.875 v1(38.443,144.875) ; U87.11@45.515,141.936 45.515,143.83 J24.4@48.96,147.275 48.96,147.46 52.85,151.35 U15.24@52.85,158.15
  Bottom Layer w0.15: v1(38.443,144.875) 39.035,144.875 39.495,145.335 47.02,145.335 J24.4@48.96,147.275
FTB_TCK: J25.5 U15.26 U61.13 | length 132.9
  Top Layer w0.15: J25.5@51.925,147.275 53.85,149.2 U15.26@53.85,158.15 ; v1(55.25,146) 57.667,146 58.142,145.525 60.883,145.525 63.1,143.308 63.1,114.157 64.057,113.2 68.9,113.2 75.6,106.5 75.6,79.175 80.604,74.171 80.604,66.01 86.926,59.689 94.791,59.689 97.064,61.962 U61.13@97.064,63.014
  INT2_SIG w0.15: J25.5@51.925,147.275 53.2,146 v1(55.25,146)
FTB_TDI: J25.4 U15.27 U61.11 | length 132
  Top Layer w0.15: U15.27@54.35,158.15 54.35,157.359 54.465,157.244 J25.4@54.465,147.275 54.465,145.76 55.487,144.738 59.702,144.738 61.9,142.54 61.9,113.2 62.7,112.4 67.4,112.4 74,105.8 74,79.555 79.725,73.83 79.725,65.495 86.356,58.864 94.815,58.864 96.34,60.389 96.689,60.389 98.364,62.064 U61.11@98.364,63.014
FTB_TDO: J25.3 U15.28 U61.14 | length 127.9
  Top Layer w0.15: U15.28@54.85,158.15 54.85,149.43 J25.3@57.005,147.275 58.381,145.899 61.427,145.899 63.9,143.425 63.9,114.2 64.461,113.639 69.861,113.639 76.53,106.97 76.53,79.071 81.05,74.551 81.05,66.182 87.168,60.064 94.742,60.064 96.414,61.736 U61.14@96.414,63.014 U61.14@96.414,63.314
FTB_TMS: J25.2 U15.29 U61.12 | length 130.9
  Top Layer w0.15: U15.29@55.35,158.15 55.35,151.475 J25.2@59.545,147.28 ; v1(57.558,145.335) 57.679,145.335 57.938,145.077 60.368,145.077 62.5,142.945 62.5,113.6 63.3,112.8 68.1,112.8 74.775,106.125 74.775,79.385 80.17,73.99 80.17,65.782 86.663,59.289 94.815,59.289 97.714,62.188 U61.12@97.714,63.014
  INT2_SIG w0.15: v1(57.558,145.335) 57.605,145.335 J25.2@59.545,147.275
FTB_TRST#: J25.1 Q31.2 R457.2 U15.30 | length 119
  Top Layer w0.15: U15.30@55.85,158.15 55.85,156.099 55.84,156.089 55.84,153.52 J25.1@62.085,147.275 ; v1(58.865,144.125) 61.4,141.59 61.4,113 62.5,111.9 67,111.9 73.2,105.7 73.2,57.495 73.62,57.075 74.384,57.075 ; R457.2@74.384,56.393 74.384,57.075 ; Q31.2@76.7,54.975 76.28,54.975 76.049,55.206 76.025,55.206 76.025,56.345 75.295,57.075 74.384,57.075
  INT2_SIG w0.15: v1(58.865,144.125) 58.935,144.125 61.835,147.025 J25.1@61.835,147.275
FTUSB_N: J23.A7 J23.B7 L14.2 U12.1 U12.6 | length 17.8
  Top Layer w0.15: v1(43.24,189.924) 43.276,189.96 43.415,189.96 43.415,189.649 43.415,189.498 42.836,188.92 42.836,188.096 U12.6@42.775,188.035 42.775,187.72 43.29,187.205 43.487,187.205 43.575,187.117 43.575,186.443 43.487,186.355 43.29,186.355 42.775,185.84 U12.1@42.775,185.525 42.788,185.512 42.788,184.695 43.575,183.908 43.575,183.518 43.487,183.43 43.425,183.43 43.3,183.305 L14.2@43.3,183.13 ; J23.A7@43.5,192.623 43.575,192.697 43.575,193.22 v1(44.015,193.66) 44.425,193.25 44.425,192.697 J23.B7@44.5,192.623
  Bottom Layer w0.15: v1(43.24,189.924) 43.469,190.154 43.469,190.398 43.152,190.715 42.12,190.715 41.76,191.075 41.76,192.383 42.14,192.762 43.117,192.762 v1(44.015,193.66)
FTUSB_P: J23.A6 J23.B6 L14.3 U12.3 U12.4 | length 17.7
  Top Layer w0.15: J23.B6@43,192.623 43.075,192.548 43.075,192.03 v1(43.52,191.585) 43.925,191.99 43.925,192.548 J23.A6@44,192.623 ; v1(44.147,189.952) 43.963,189.768 43.963,189.478 44.236,189.205 44.236,189.198 44.576,188.857 44.576,188.134 U12.4@44.675,188.035 44.675,187.72 44.16,187.205 43.963,187.205 43.875,187.117 43.875,186.443 43.963,186.355 44.16,186.355 44.675,185.84 U12.3@44.675,185.525 44.662,185.512 44.662,184.695 43.875,183.908 43.875,183.518 43.963,183.43 44.025,183.43 44.15,183.305 L14.3@44.15,183.13
  Bottom Layer w0.15: v1(43.52,191.585) 43.434,191.671 43.434,192.067 43.039,192.462 42.264,192.462 42.06,192.258 42.06,192.122 42.06,191.889 42.148,191.801 42.447,191.801 42.534,191.713 42.534,191.538 42.447,191.451 42.148,191.451 42.06,191.363 42.06,191.199 42.234,191.026 42.245,191.015 43.276,191.015 43.769,190.522 43.769,190.329 v1(44.147,189.952)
